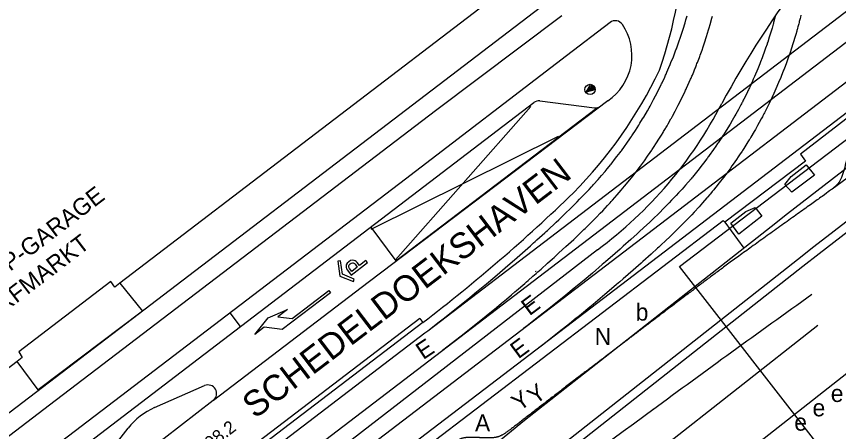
# Model space of a CAD drawing. Extents: x 81617 to 82144, y 454649 to 455150.
# Drawn here: x 81877.73 to 81925.8, y 454945.52 to 454969.8 of the extents above; entities that cross this region are included whole.
import ezdxf

# ---------------------------------------------------------------- set-up
doc = ezdxf.new("R2010")
doc.units = 0
for name, color, linetype in [('B-WE-OG-TOPOGRAFIE-G', 7, 'Continuous'), ('B-WE-VW-MARKERING-G', 7, 'Continuous'), ('N-OI-KL-VRI_KABELGEUL-G', 7, 'Continuous'), ('N-OI-KL-VRI_LUS_DETECTIE-T18', 7, 'Continuous')]:
    doc.layers.add(name, color=color, linetype=linetype)

msp = doc.modelspace()

# ---------------------------------------------------------------- linework, layer by layer
at = {"layer": 'B-WE-OG-TOPOGRAFIE-G'}
for p, q in [((81859.516, 454933.039), (81910.646, 454972.096)), ((81888.032, 454949.528), (81907.977, 454964.762)), ((81888.032, 454949.528), (81907.977, 454964.762)), ((81908.341, 454964.861), (81911.534, 454964.467)), ((81916.494, 454955.166), (81927.173, 454963.304)), ((81900.482, 454960.292), (81880.371, 454944.941)), ((81921.863, 454957.505), (81907.441, 454946.156)), ((81919.157, 454957.774), (81920.254, 454956.239)), ((81923.402, 454955.563), (81908.992, 454944.223)), ((81923.712, 454955.17), (81909.304, 454943.832)), ((81925.37, 454943.778), (81916.494, 454955.166)), ((81883.244, 454954.301), (81877.871, 454950.19)), ((81883.781, 454954.209), (81885.099, 454952.555)), ((81890.824, 454951.661), (81890.233, 454952.469)), ((81901.315, 454952.138), (81901.497, 454951.9)), ((81927.735, 454950.065), (81913.364, 454938.756)), ((81881.134, 454944.252), (81888.032, 454949.528)), ((81885.808, 454946.922), (81888.733, 454948.203)), ((81883.083, 454942.614), (81889.238, 454947.349)), ((81907.441, 454946.156), (81891.612, 454933.292)), ((81882.384, 454943.318), (81884.261, 454945.72))]:
    msp.add_line(p, q, dxfattribs=at)
for points in [[(81873.49, 454927.861), (81874.235, 454928.464), (81874.684, 454928.824), (81874.834, 454928.943), (81875.133, 454929.183), (81876.035, 454929.897), (81876.336, 454930.134), (81876.944, 454930.61), (81877.553, 454931.084), (81877.859, 454931.32), (81878.164, 454931.557), (81879.083, 454932.264), (81879.697, 454932.734), (81880.618, 454933.44), (81881.483, 454934.1), (82053.484, 455065.539)], [(82052.863, 455062.717), (81907.219, 454951.42), (81881.918, 454932.086), (81881.368, 454931.665), (81879.897, 454930.54), (81879.014, 454929.861), (81878.133, 454929.178), (81876.818, 454928.147), (81876.529, 454927.916), (81876.383, 454927.802), (81875.945, 454927.452), (81875.222, 454926.872), (81874.931, 454926.636), (81874.646, 454926.404), (81874.501, 454926.287), (81873.923, 454925.815), (81873.138, 454925.168), (81872.64, 454924.754), (81871.896, 454924.132), (81871.4, 454923.716), (81870.675, 454923.104)], [(82053.734, 455061.577), (81908.09, 454950.28), (81882.79, 454930.946), (81882.24, 454930.525), (81880.77, 454929.401), (81879.891, 454928.725), (81879.015, 454928.046), (81877.708, 454927.021), (81877.419, 454926.791), (81877.274, 454926.677), (81876.842, 454926.332), (81876.122, 454925.754), (81875.835, 454925.522), (81875.549, 454925.289), (81875.405, 454925.173), (81874.834, 454924.706), (81874.053, 454924.062), (81873.558, 454923.651), (81872.817, 454923.032), (81872.324, 454922.618), (81871.758, 454922.14)], [(81886.379, 454998.242), (81903.394, 454975.978), (81906.664, 454971.698), (81883.781, 454954.209)], [(81877.287, 454932.693), (81878.516, 454933.638), (81879.132, 454934.109), (81879.439, 454934.345), (81887.3, 454940.351), (81901.614, 454951.29), (81901.778, 454951.416), (81947.621, 454986.447)], [(81939.478, 454974.048), (81923.575, 454961.742), (81923.877, 454961.345), (81919.157, 454957.774)], [(81923.602, 454969.883), (81923.57, 454969.757), (81923.555, 454969.693), (81923.523, 454969.567), (81923.506, 454969.504), (81923.49, 454969.441), (81923.473, 454969.378), (81923.457, 454969.315), (81923.423, 454969.19), (81923.405, 454969.127), (81923.374, 454969.013), (81923.37, 454969.002), (81923.353, 454968.939), (81923.299, 454968.751), (81923.28, 454968.689), (81923.262, 454968.626), (81923.148, 454968.253), (81923.028, 454967.881), (81922.986, 454967.758), (81922.966, 454967.696), (81922.945, 454967.634), (81922.923, 454967.573), (81922.881, 454967.45), (81922.837, 454967.327)], [(81860.336, 454932.309), (81879.668, 454947.077), (81902.238, 454964.298), (81909.611, 454969.854)], [(81912.444, 454969.453), (81909.889, 454967.496), (81900.482, 454960.292)], [(81914.776, 454964.558), (81914.836, 454964.666), (81914.982, 454964.936), (81915.097, 454965.154), (81915.292, 454965.537), (81915.427, 454965.814), (81915.453, 454965.869), (81915.48, 454965.924), (81915.636, 454966.259), (81915.686, 454966.371), (81915.712, 454966.427), (81915.762, 454966.539), (81915.884, 454966.821), (81915.956, 454966.991), (81915.979, 454967.048), (81916.003, 454967.104), (81916.141, 454967.447), (81916.163, 454967.504), (81916.186, 454967.561), (81916.252, 454967.733), (81916.273, 454967.791), (81916.295, 454967.848), (81916.316, 454967.906), (81916.401, 454968.137), (81916.421, 454968.195), (81916.442, 454968.253), (81916.462, 454968.311), (81916.483, 454968.369), (81916.543, 454968.543), (81916.601, 454968.718), (81916.621, 454968.776), (81916.659, 454968.893), (81916.677, 454968.952), (81916.715, 454969.069), (81916.823, 454969.422), (81916.874, 454969.599), (81916.892, 454969.658), (81916.908, 454969.717), (81916.942, 454969.835)], [(81915.999, 454963.805), (81916.031, 454963.861), (81916.094, 454963.975), (81916.249, 454964.262), (81916.31, 454964.377), (81916.43, 454964.608), (81916.576, 454964.898), (81916.663, 454965.074), (81916.804, 454965.367), (81916.831, 454965.426), (81916.859, 454965.485), (81916.886, 454965.544), (81916.914, 454965.603), (81916.995, 454965.781), (81917.153, 454966.138), (81917.178, 454966.198), (81917.204, 454966.258), (81917.229, 454966.318), (81917.255, 454966.378), (81917.33, 454966.558), (81917.403, 454966.739), (81917.428, 454966.799), (81917.5, 454966.981), (81917.523, 454967.042), (81917.547, 454967.102), (81917.662, 454967.407), (81917.684, 454967.468), (81917.707, 454967.529), (81917.817, 454967.836), (81917.88, 454968.02), (81917.902, 454968.082), (81917.964, 454968.267), (81918.084, 454968.639), (81918.198, 454969.012), (81918.216, 454969.075), (81918.235, 454969.137), (81918.289, 454969.325), (81918.393, 454969.701), (81918.409, 454969.764)], [(81918.409, 454969.764), (81918.426, 454969.827)], [(81922.102, 454969.805), (81922.006, 454969.449), (81921.992, 454969.401), (81921.981, 454969.36), (81921.913, 454969.124), (81921.895, 454969.065), (81921.878, 454969.006), (81921.788, 454968.712), (81921.769, 454968.654), (81921.751, 454968.595), (81921.656, 454968.303), (81921.636, 454968.245), (81921.617, 454968.186), (81921.537, 454967.954), (81921.516, 454967.896), (81921.496, 454967.838), (81921.454, 454967.722)], [(81939.724, 454968.187), (81924.357, 454956.316), (81923.402, 454955.563)], [(81921.454, 454967.722), (81921.37, 454967.491), (81921.348, 454967.434), (81921.327, 454967.376), (81921.239, 454967.147), (81921.216, 454967.09), (81921.194, 454967.032), (81921.079, 454966.747), (81920.888, 454966.294), (81920.813, 454966.125), (81920.789, 454966.069), (81920.763, 454966.013), (81920.713, 454965.901), (81920.687, 454965.845), (81920.662, 454965.789), (81920.584, 454965.622), (81920.557, 454965.567), (81920.531, 454965.511), (81920.504, 454965.456), (81920.478, 454965.4), (81920.37, 454965.18), (81920.259, 454964.96), (81920.232, 454964.905), (81920.175, 454964.796), (81920.147, 454964.741), (81920.118, 454964.687), (81920.09, 454964.632), (81919.945, 454964.362), (81919.796, 454964.092), (81919.736, 454963.985), (81919.583, 454963.719), (81919.458, 454963.507), (81919.234, 454963.14), (81919.168, 454963.036), (81919.07, 454962.88), (81919.003, 454962.777), (81918.97, 454962.725), (81918.835, 454962.52), (81918.8, 454962.469), (81918.766, 454962.417), (81918.732, 454962.367)], [(81940.03, 454967.792), (81924.665, 454955.922), (81923.712, 454955.17)], [(81922.837, 454967.327), (81922.749, 454967.082), (81922.611, 454966.717), (81922.587, 454966.656), (81922.564, 454966.595), (81922.468, 454966.353), (81922.443, 454966.293), (81922.419, 454966.233), (81922.294, 454965.932), (81922.139, 454965.574), (81921.951, 454965.159), (81921.923, 454965.1), (81921.896, 454965.041), (81921.756, 454964.747), (81921.583, 454964.397), (81921.464, 454964.165), (81921.435, 454964.107), (81921.374, 454963.992), (81921.344, 454963.934), (81921.313, 454963.877), (81921.283, 454963.819), (81921.159, 454963.59), (81921.064, 454963.419), (81920.936, 454963.193), (81920.871, 454963.08), (81920.673, 454962.743), (81920.605, 454962.632), (81920.572, 454962.576), (81920.504, 454962.465), (81920.261, 454962.079), (81920.19, 454961.97), (81920.155, 454961.915), (81920.012, 454961.698), (81919.939, 454961.59)], [(81934.471, 454967.261), (81922.825, 454958.264), (81921.863, 454957.505)], [(81911.318, 454965.811), (81911.548, 454965.511), (81911.047, 454965.367), (81911.283, 454965.763), (81911.452, 454965.543), (81911.149, 454965.445), (81911.288, 454965.657), (81911.352, 454965.575), (81911.292, 454965.554), (81911.231, 454965.51)], [(81912.306, 454964.876), (81899.101, 454954.842), (81898.292, 454954.231), (81889.243, 454947.343)], [(81910.658, 454959.105), (81910.798, 454959.248), (81911.005, 454959.464), (81911.211, 454959.682), (81911.346, 454959.828), (81911.413, 454959.902), (81911.481, 454959.975), (81911.746, 454960.271), (81911.942, 454960.496), (81912.15, 454960.741), (81912.268, 454960.882), (81912.385, 454961.025), (81912.462, 454961.121), (81912.501, 454961.168), (81912.767, 454961.507), (81912.842, 454961.604), (81913.027, 454961.849), (81913.063, 454961.899), (81913.1, 454961.948), (81913.281, 454962.197), (81913.423, 454962.397), (81913.598, 454962.65), (81913.667, 454962.752), (81913.686, 454962.779), (81913.718, 454962.828), (81913.753, 454962.879), (81913.922, 454963.136), (81914.12, 454963.447), (81914.185, 454963.551), (81914.249, 454963.656), (81914.282, 454963.708), (81914.345, 454963.814), (81914.409, 454963.919), (81914.626, 454964.291), (81914.717, 454964.451), (81914.776, 454964.558)], [(81911.647, 454958.063), (81911.865, 454958.287), (81912.009, 454958.437), (81912.295, 454958.741), (81912.437, 454958.894), (81912.507, 454958.972), (81912.578, 454959.049), (81912.718, 454959.205), (81912.857, 454959.361), (81913.097, 454959.639), (81913.291, 454959.868), (81913.498, 454960.119), (81913.58, 454960.22), (81913.782, 454960.475), (81914.021, 454960.784), (81914.139, 454960.94), (81914.216, 454961.045), (81914.332, 454961.202), (81914.447, 454961.36), (81914.635, 454961.626), (81914.783, 454961.84), (81914.876, 454961.977), (81914.91, 454962.029), (81914.983, 454962.137), (81915.161, 454962.41), (81915.301, 454962.629), (81915.404, 454962.795), (81915.439, 454962.85), (81915.541, 454963.017), (81915.574, 454963.073), (81915.608, 454963.128), (81915.674, 454963.24), (81915.708, 454963.296), (81915.773, 454963.409), (81915.839, 454963.521), (81915.999, 454963.805)], [(81918.732, 454962.367), (81918.628, 454962.214), (81918.488, 454962.012), (81918.238, 454961.662), (81918.201, 454961.613), (81918.165, 454961.563), (81918.128, 454961.514), (81918.092, 454961.464), (81917.907, 454961.219), (81917.832, 454961.121), (81917.566, 454960.783), (81917.411, 454960.592), (81917.255, 454960.403), (81917.215, 454960.356), (81917.176, 454960.308), (81916.846, 454959.925), (81916.648, 454959.703), (81916.447, 454959.482), (81916.312, 454959.336), (81916.243, 454959.264), (81916.175, 454959.191), (81916.038, 454959.047), (81915.899, 454958.903), (81915.619, 454958.618), (81915.264, 454958.265), (81914.976, 454957.986), (81914.758, 454957.778), (81914.391, 454957.433), (81914.169, 454957.228), (81914.094, 454957.16), (81914.02, 454957.091), (81913.646, 454956.751), (81913.214, 454956.363)], [(81919.939, 454961.59), (81919.829, 454961.428), (81919.644, 454961.161), (81919.568, 454961.055), (81919.455, 454960.896), (81919.378, 454960.791), (81919.34, 454960.738), (81919.067, 454960.373), (81918.828, 454960.065), (81918.625, 454959.81), (81918.543, 454959.709), (81918.501, 454959.659), (81918.419, 454959.558), (81918.309, 454959.427), (81918.273, 454959.383), (81918.146, 454959.235), (81918.104, 454959.185), (81917.854, 454958.899), (81917.644, 454958.665), (81917.361, 454958.357), (81917.217, 454958.205), (81917.146, 454958.129), (81916.856, 454957.829), (81916.637, 454957.606), (81916.563, 454957.533), (81916.49, 454957.459), (81916.268, 454957.24), (81916.193, 454957.168), (81916.119, 454957.095), (81915.97, 454956.951), (81915.67, 454956.666), (81915.444, 454956.453), (81915.292, 454956.313), (81915.217, 454956.242), (81914.837, 454955.894), (81914.36, 454955.463), (81914.265, 454955.378)], [(81923.06, 454959.526), (81922.666, 454959.964), (81923.024, 454960.446), (81923.898, 454961.132), (81924.395, 454960.511), (81923.06, 454959.526)], [(81901.778, 454951.416), (81902.178, 454951.722), (81902.377, 454951.876), (81902.674, 454952.109), (81902.774, 454952.186), (81903.366, 454952.654), (81903.955, 454953.127), (81904.15, 454953.286), (81904.248, 454953.365), (81904.637, 454953.684), (81905.218, 454954.167), (81905.699, 454954.572), (81905.987, 454954.817), (81906.464, 454955.227), (81906.844, 454955.558), (81907.316, 454955.973), (81907.786, 454956.392), (81907.973, 454956.56), (81908.066, 454956.645), (81908.16, 454956.729), (81908.625, 454957.153), (81908.699, 454957.222), (81908.774, 454957.29), (81909.292, 454957.772), (81909.439, 454957.91), (81909.803, 454958.258), (81910.163, 454958.608), (81910.305, 454958.75), (81910.518, 454958.962), (81910.658, 454959.105)], [(81919.499, 454957.702), (81920.372, 454958.387), (81920.924, 454958.621), (81921.32, 454958.113), (81919.979, 454957.068), (81919.499, 454957.702)], [(81902.65, 454950.275), (81903.408, 454950.86), (81903.91, 454951.254), (81904.609, 454951.811), (81905.006, 454952.132), (81905.204, 454952.294), (81905.402, 454952.455), (81905.697, 454952.699), (81905.796, 454952.78), (81906.09, 454953.026), (81906.188, 454953.107), (81906.383, 454953.272), (81906.676, 454953.519), (81906.87, 454953.685), (81906.967, 454953.767), (81907.451, 454954.184), (81907.547, 454954.268), (81907.644, 454954.351), (81907.932, 454954.603), (81908.124, 454954.772), (81908.219, 454954.857), (81908.411, 454955.026), (81908.791, 454955.366), (81909.076, 454955.623), (81909.17, 454955.709), (81909.265, 454955.794), (81909.454, 454955.966), (81909.86, 454956.34), (81910.312, 454956.761), (81910.537, 454956.974), (81910.687, 454957.117), (81910.91, 454957.332), (81910.984, 454957.405), (81911.059, 454957.477), (81911.28, 454957.695), (81911.574, 454957.989), (81911.647, 454958.063)], [(81873.083, 454921.869), (81875.385, 454923.83), (81882.216, 454929.671), (81883.773, 454930.953), (81919.061, 454957.857), (81919.157, 454957.774)], [(81913.214, 454956.363), (81913.12, 454956.279), (81913.025, 454956.196), (81912.742, 454955.945), (81912.173, 454955.447), (81912.077, 454955.365), (81911.982, 454955.282), (81911.408, 454954.79), (81910.926, 454954.383), (81910.733, 454954.221), (81910.345, 454953.899), (81909.858, 454953.499), (81909.27, 454953.023), (81908.777, 454952.63), (81908.282, 454952.24), (81908.182, 454952.163), (81908.083, 454952.085), (81907.983, 454952.008), (81907.884, 454951.93), (81907.584, 454951.699), (81907.384, 454951.546)], [(81914.265, 454955.378), (81913.787, 454954.953), (81913.21, 454954.447), (81913.016, 454954.28), (81912.823, 454954.112), (81912.532, 454953.863), (81912.142, 454953.531), (81911.456, 454952.956), (81911.357, 454952.875), (81911.259, 454952.793), (81910.765, 454952.387), (81910.566, 454952.226), (81910.467, 454952.145), (81910.068, 454951.824), (81909.468, 454951.347), (81909.065, 454951.031), (81908.661, 454950.718), (81908.56, 454950.639), (81908.255, 454950.406)], [(81883.781, 454954.209), (81883.473, 454953.974), (81883.244, 454954.301)], [(81901.315, 454952.138), (81867.262, 454926.143)], [(81885.099, 454952.555), (81878.996, 454947.968), (81877.773, 454949.621)], [(81901.497, 454951.9), (81867.49, 454925.94)], [(81877.871, 454950.19), (81878.072, 454949.85), (81877.773, 454949.621)], [(81877.773, 454949.621), (81857.927, 454934.453)]]:
    msp.add_lwpolyline(points, dxfattribs=at)
msp.add_circle((81911.268, 454965.536), 0.3, dxfattribs=at)
for centre, radius, start, end in [((81891.435, 454975.03), 25.32, 340.6848, 358.9647), ((81912.748, 454969.056), 0.5, 34.5214, 127.4534), ((81910.528, 454967.529), 3.194, 303.8284, 34.5214), ((81891.116, 454978.283), 26.861, 315.564, 334.3506), ((81908.28, 454964.364), 0.5, 82.9718, 127.3723), ((81911.595, 454964.963), 0.5, 262.9718, 307.228), ((81839.637, 455032.631), 101.706, 307.46074, 314.00577), ((81888.933, 454947.745), 0.5, 307.5725, 113.6545), ((81887.413, 454943.258), 4, 113.6545, 142.0128)]:
    msp.add_arc(centre, radius, start, end, dxfattribs=at)
at = {"layer": 'B-WE-VW-MARKERING-G'}
for p, q in [((81899.9, 454955.561), (81907.812, 454964.535)), ((81898.465, 454957.366), (81909.429, 454962.798)), ((81911.696, 454956.155), (81875.824, 454928.411)), ((81896.795, 454954.733), (81896.67, 454955.503)), ((81897.485, 454954.435), (81896.795, 454954.733)), ((81896.096, 454953.642), (81893.275, 454951.488)), ((81893.859, 454952.123), (81896.005, 454953.762)), ((81896.005, 454953.762), (81896.096, 454953.642)), ((81892.439, 454952.171), (81893.575, 454952.661)), ((81893.575, 454952.661), (81893.018, 454952.236)), ((81891.667, 454951.204), (81892.439, 454952.171)), ((81893.018, 454952.236), (81893.859, 454952.123)), ((81892.223, 454951.629), (81891.667, 454951.204)), ((81893.275, 454951.488), (81892.223, 454951.629)), ((81924.585, 454951.725), (81914.212, 454943.562))]:
    msp.add_line(p, q, dxfattribs=at)
for points in [[(81898.445, 454957.481), (81899.908, 454955.515), (81911.643, 454964.429)], [(81896.67, 454955.503), (81896.522, 454955.483), (81896.642, 454954.616)], [(81896.642, 454954.616), (81897.429, 454954.296), (81897.485, 454954.435)], [(81908.087, 454954.877), (81908.11, 454954.895)], [(81908.107, 454954.893), (81908.11, 454954.895)]]:
    msp.add_lwpolyline(points, dxfattribs=at)
for points in [[(81897.158, 454955.456), (81897.157, 454955.455), (81897.071, 454955.37), (81897.018, 454955.27), (81897.003, 454955.193), (81897.008, 454955.116), (81897.035, 454955.039), (81897.083, 454954.962), (81897.302, 454954.676), (81898.255, 454955.404), (81898.164, 454955.523), (81897.786, 454955.235), (81897.66, 454955.4), (81897.603, 454955.461), (81897.541, 454955.505), (81897.471, 454955.531), (81897.395, 454955.54), (81897.272, 454955.518)], [(81897.249, 454955.336), (81897.308, 454955.369), (81897.374, 454955.384), (81897.419, 454955.381), (81897.461, 454955.367), (81897.499, 454955.342), (81897.533, 454955.306), (81897.66, 454955.138), (81897.337, 454954.891), (81897.209, 454955.059), (81897.167, 454955.135), (81897.159, 454955.206), (81897.187, 454955.273)]]:
    msp.add_lwpolyline(points, close=True, dxfattribs=at)
for centre, radius, start, end in [((81968.831, 454937.782), 56.668, 142.4843, 151.6344), ((81897.184, 454975.862), 24.474, 306.3671, 332.8777), ((82446.303, 454224.11), 897, 125.592347, 126.327511), ((82446.303, 454224.11), 897, 126.319161, 129.387113)]:
    msp.add_arc(centre, radius, start, end, dxfattribs=at)
at = {"layer": 'N-OI-KL-VRI_KABELGEUL-G'}
msp.add_lwpolyline([(81969.078, 454991.751), (81925.426, 454959.701)], dxfattribs=at)
msp.add_open_spline([(81966.954, 454994.044), (81954.516, 454984.42), (81942.079, 454974.796), (81941.008, 454974.125), (81939.937, 454973.455), (81933.631, 454968.575), (81927.325, 454963.696), (81926.798, 454963.288), (81926.621, 454962.646), (81926.355, 454961.682), (81926.09, 454960.718), (81925.901, 454960.035), (81925.325, 454959.623), (81922.434, 454957.557), (81919.543, 454955.49), (81917.87, 454954.23), (81916.197, 454952.97), (81913.406, 454950.849), (81910.615, 454948.728), (81908.564, 454947.145), (81906.513, 454945.562), (81905.944, 454945.123), (81905.225, 454945.147), (81904.815, 454945.16), (81904.405, 454945.174), (81903.693, 454945.197), (81903.126, 454944.765), (81893.683, 454937.565), (81884.239, 454930.365), (81883.469, 454929.731), (81882.698, 454929.096), (81879.285, 454926.178), (81875.872, 454923.259), (81872.421, 454920.321), (81868.97, 454917.382), (81867.082, 454915.724), (81865.195, 454914.067), (81863.45, 454912.271), (81861.704, 454910.475), (81860.838, 454909.482), (81859.972, 454908.49), (81859.86, 454908.361), (81859.97, 454908.23), (81860.094, 454908.077), (81860.218, 454907.925), (81863.368, 454903.762), (81866.518, 454899.599), (81866.598, 454899.497), (81866.679, 454899.395)], degree=4, dxfattribs=at)

# ---------------------------------------------------------------- texts
at = {"layer": 'B-WE-OG-TOPOGRAFIE-G'}
for s, height, rotation, p in [('SCHEDELDOEKSHAVEN', 1.5, 37.3305, (81891.677, 454946.225)), ('TOEGANG P-GARAGE', 1, 37.3592, (81871.753, 454950.582)), ('TURFMARKT', 1, 37.3592, (81875.532, 454951.328)), ('E', 1, 37.0556, (81907.729, 454952.254)), ('E', 1, 33.802, (81901.517, 454949.693)), ('E', 1, 36.5241, (81907.078, 454949.736)), ('Y', 1, 37.0862, (81908.08, 454947.061)), ('Y', 1, 36.2062, (81907.143, 454946.67))]:
    msp.add_text(s, height=height, rotation=rotation, dxfattribs=at).set_placement(p)
for s, p in [('b', (81913.937, 454952.008)), ('N', (81911.543, 454950.584)), ('e', (81925.346, 454947.249)), ('e', (81924.279, 454946.409)), ('A', (81904.54, 454945.522)), ('e', (81923.212, 454945.57))]:
    msp.add_text(s, height=1, dxfattribs=at).set_placement(p)
at = {"layer": 'N-OI-KL-VRI_LUS_DETECTIE-T18'}
msp.add_text('D08.2', height=0.75, rotation=37.3715, dxfattribs=at).set_placement((81888.515, 454944.006))

doc.saveas('drawing.dxf')
